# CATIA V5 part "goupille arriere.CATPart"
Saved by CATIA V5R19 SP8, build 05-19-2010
Part number: goupille arrière
Bounding box of the stored display mesh (mm): x 0 to 26.2, y -1.5 to 1.5, z -1.5 to 1.5
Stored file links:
  C:\Users\Arthur\Desktop\Catia parts\GLOCK\Poignée\goupille arriere.CATPart
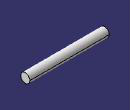
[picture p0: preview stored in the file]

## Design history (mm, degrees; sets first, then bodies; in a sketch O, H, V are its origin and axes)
Set1
  Sketch1 on yz-plane, origin (0, 0, 0), H (0, 1, 0), V (0, 0, 1)
    circle A1 centre (0, 0) radius 1.5
    radius A1 = 1.5
Body1 (main body)
  Pad1: profile Sketch1, direction (1, 0, 0), length 26.2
